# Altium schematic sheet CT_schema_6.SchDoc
size 479 x 328 mm
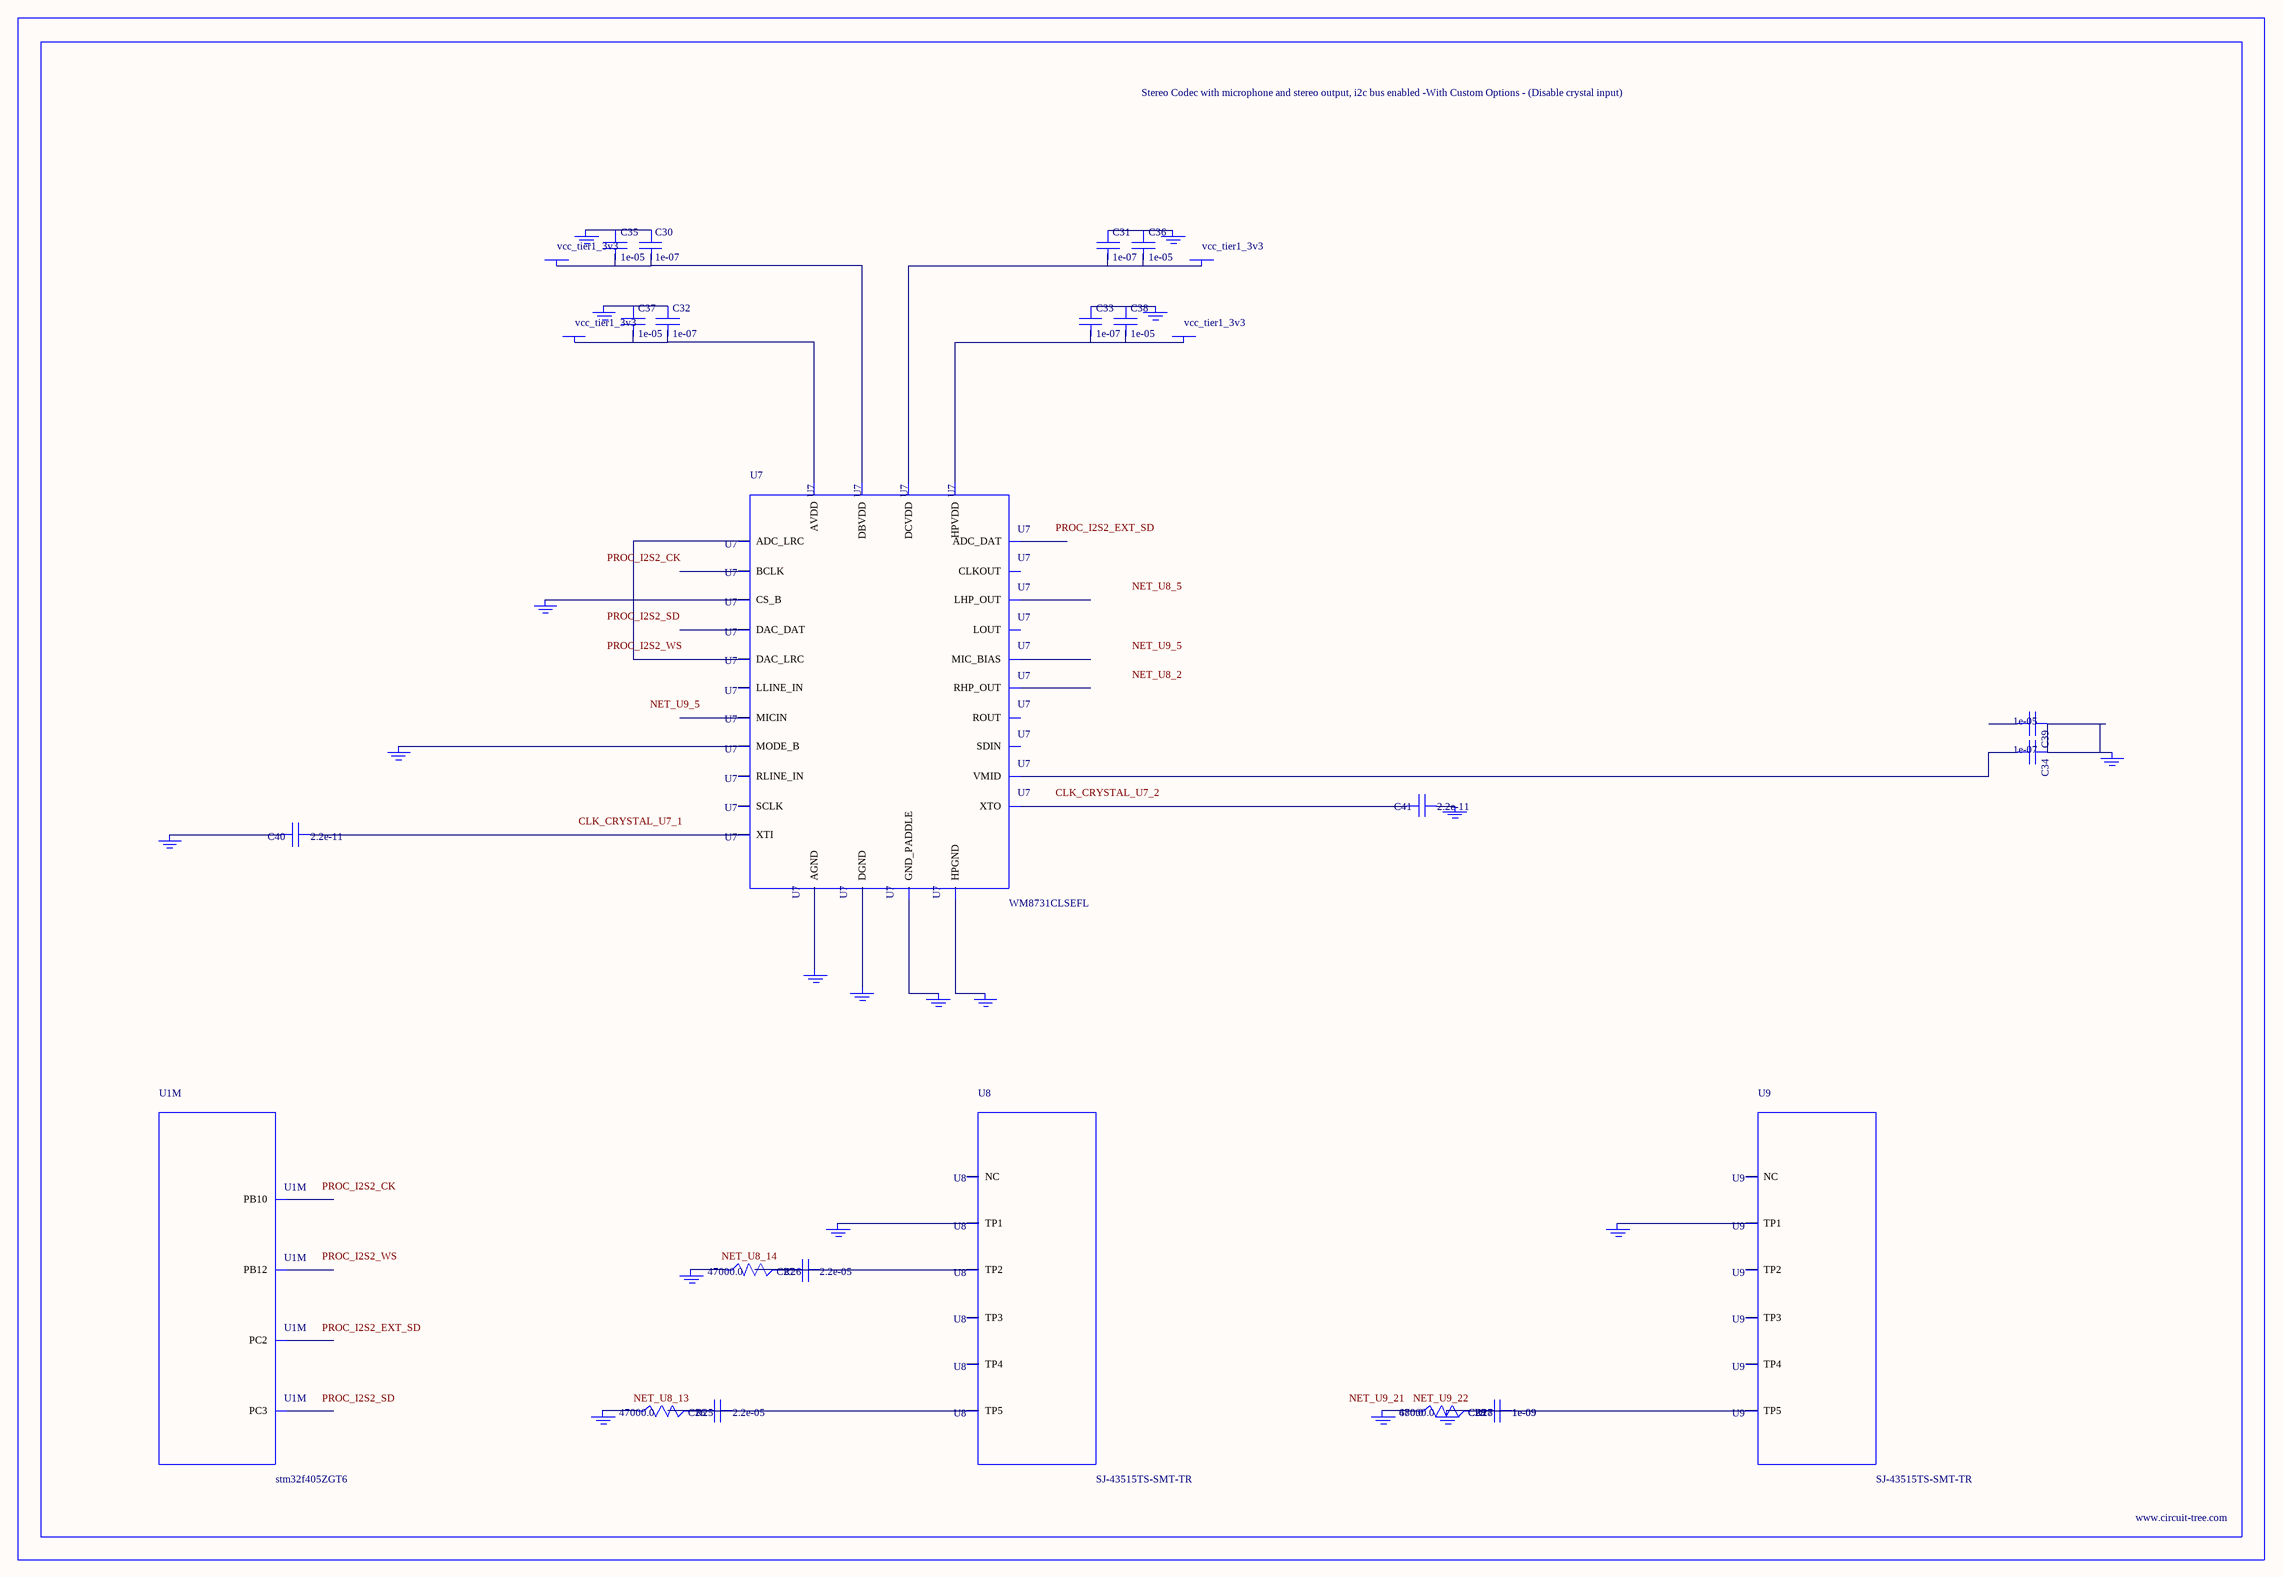
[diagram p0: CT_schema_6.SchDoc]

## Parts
BORDER5  (no value)
C26  2.2e-05  [C1210]
C27  2.2e-05  [C1210]
C28  1e-09  [C0402]
C29  1e-09  [C0402]
C30  1e-07  [C0402]
C31  1e-07  [C0402]
C32  1e-07  [C0402]
C33  1e-07  [C0402]
C34  1e-07  [C0402]
C35  1e-05  [C0805]
C36  1e-05  [C0805]
C37  1e-05  [C0805]
C38  1e-05  [C0805]
C39  1e-05  [C0805]
C40  2.2e-11  [C0402]
C41  2.2e-11  [C0402]
GND_INSTANCE_5_0  (no value)
GND_INSTANCE_5_1  (no value)
GND_INSTANCE_5_2  (no value)
GND_INSTANCE_5_3  (no value)
GND_INSTANCE_5_4  (no value)
GND_INSTANCE_5_5  (no value)
GND_INSTANCE_5_6  (no value)
GND_INSTANCE_5_7  (no value)
GND_INSTANCE_5_8  (no value)
GND_INSTANCE_5_9  (no value)
GND_INSTANCE_5_10  (no value)
GND_INSTANCE_5_11  (no value)
GND_INSTANCE_5_12  (no value)
GND_INSTANCE_5_13  (no value)
GND_INSTANCE_5_14  (no value)
GND_INSTANCE_5_15  (no value)
GND_INSTANCE_5_16  (no value)
GND_INSTANCE_5_17  (no value)
GND_INSTANCE_5_18  (no value)
POWER_INSTANCE_5_0  vcc_tier1_3v3
POWER_INSTANCE_5_1  vcc_tier1_3v3
POWER_INSTANCE_5_2  vcc_tier1_3v3
POWER_INSTANCE_5_3  vcc_tier1_3v3
R25  47000.0  [R0603]
R26  47000.0  [R0603]
R27  47000.0  [R0603]
R28  680.0  [R0603]
U1  stm32f405ZGT6  [LQFP144]  (part M of 13)
U7  WM8731CLSEFL  [QFN-28]
U8  SJ-43515TS-SMT-TR  [SJ-43515TS-SMT-TR]
U9  SJ-43515TS-SMT-TR  [SJ-43515TS-SMT-TR]

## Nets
NetC26_1: C26.1 C26.2 R25.2 U8.5(TP5)
NetC27_1: C27.1 C27.2 R26.2 U8.2(TP2)
NetC28_1: C28.1 C28.2 C29.1 C29.2 GND_INSTANCE_5_18.0(GND) R27.2 R28.2 U9.5(TP5)
NetC30_1: C30.1 C35.1 GND_INSTANCE_5_3.0(GND)
NetC30_2: C30.2 C35.2 POWER_INSTANCE_5_1.0(PWR) U7.5(DBVDD)
NetC31_1: C31.1 C36.1 GND_INSTANCE_5_2.0(GND)
NetC31_2: C31.2 C36.2 POWER_INSTANCE_5_0.0(PWR) U7.3(DCVDD)
NetC32_1: C32.1 C37.1 GND_INSTANCE_5_6.0(GND)
NetC32_2: C32.2 C37.2 POWER_INSTANCE_5_3.0(PWR) U7.18(AVDD)
NetC33_1: C33.1 C38.1 GND_INSTANCE_5_4.0(GND)
NetC33_2: C33.2 C38.2 POWER_INSTANCE_5_2.0(PWR) U7.12(HPVDD)
NetC34_1: C34.1 C39.1 GND_INSTANCE_5_7.0(GND)
NetC34_2: C34.2 U7.20(VMID)
NetC40_1: C40.1 U7.1(XTI)
NetC40_2: C40.2 GND_INSTANCE_5_0.0(GND)
NetC41_1: C41.1 GND_INSTANCE_5_1.0(GND)
NetC41_2: C41.2 U7.2(XTO)
NetGND_INSTANCE_5_5_0: GND_INSTANCE_5_5.0(GND) U7.15(HPGND)
NetGND_INSTANCE_5_8_0: GND_INSTANCE_5_8.0(GND) U7.25(MODE_B)
NetGND_INSTANCE_5_9_0: GND_INSTANCE_5_9.0(GND) U7.26(CS_B)
NetGND_INSTANCE_5_10_0: GND_INSTANCE_5_10.0(GND) U7.29(GND_PADDLE)
NetGND_INSTANCE_5_11_0: GND_INSTANCE_5_11.0(GND) U7.4(DGND)
NetGND_INSTANCE_5_12_0: GND_INSTANCE_5_12.0(GND) U7.19(AGND)
NetGND_INSTANCE_5_13_0: GND_INSTANCE_5_13.0(GND) U8.1(TP1)
NetGND_INSTANCE_5_14_0: GND_INSTANCE_5_14.0(GND) R26.1
NetGND_INSTANCE_5_15_0: GND_INSTANCE_5_15.0(GND) R25.1
NetGND_INSTANCE_5_16_0: GND_INSTANCE_5_16.0(GND) U9.1(TP1)
NetGND_INSTANCE_5_17_0: GND_INSTANCE_5_17.0(GND) R27.1 R28.1
NetU7_9: U7.9(DAC_LRC) U7.11(ADC_LRC)

Not connected (* = marked no-connect by the designer): C39 2; U1 28(PC2) 29(PC3) 69(PB10) 73(PB12); U7 6(CLKOUT) 7(BCLK) 8(DAC_DAT) 10(ADC_DAT) 13(LHP_OUT) 14(RHP_OUT) 16(LOUT) 17(ROUT) 21(MIC_BIAS) 22(MICIN) 23(RLINE_IN) 24(LLINE_IN) 27(SDIN) 28(SCLK); U8 3(TP3) 4(TP4) 6(NC); U9 2(TP2) 3(TP3) 4(TP4) 6(NC)

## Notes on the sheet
- Labels drawn without touching a wire or pin: CLK_CRYSTAL_U7_1, CLK_CRYSTAL_U7_2, NET_U8_2, NET_U8_5, NET_U8_13, NET_U8_14, NET_U9_5, NET_U9_21, NET_U9_22, PROC_I2S2_CK, PROC_I2S2_EXT_SD, PROC_I2S2_SD, PROC_I2S2_WS

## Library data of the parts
BORDER5 = BORDER_PAGE5
C26 C27 = C1210C224K5RACTU
C28 C29 = C0402C102K3RAC
C30-C34 = C0402C104K3RACTU
C35-C39 = C0805C106K8RACTU
C40 C41 = C0402C220K3RAC
GND_INSTANCE_5_0-GND_INSTANCE_5_18 = GND
POWER_INSTANCE_5_0-POWER_INSTANCE_5_3 = PWR
R25-R27 = RC0603JR-0747KL
R28 = RC0603JR-07680RL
